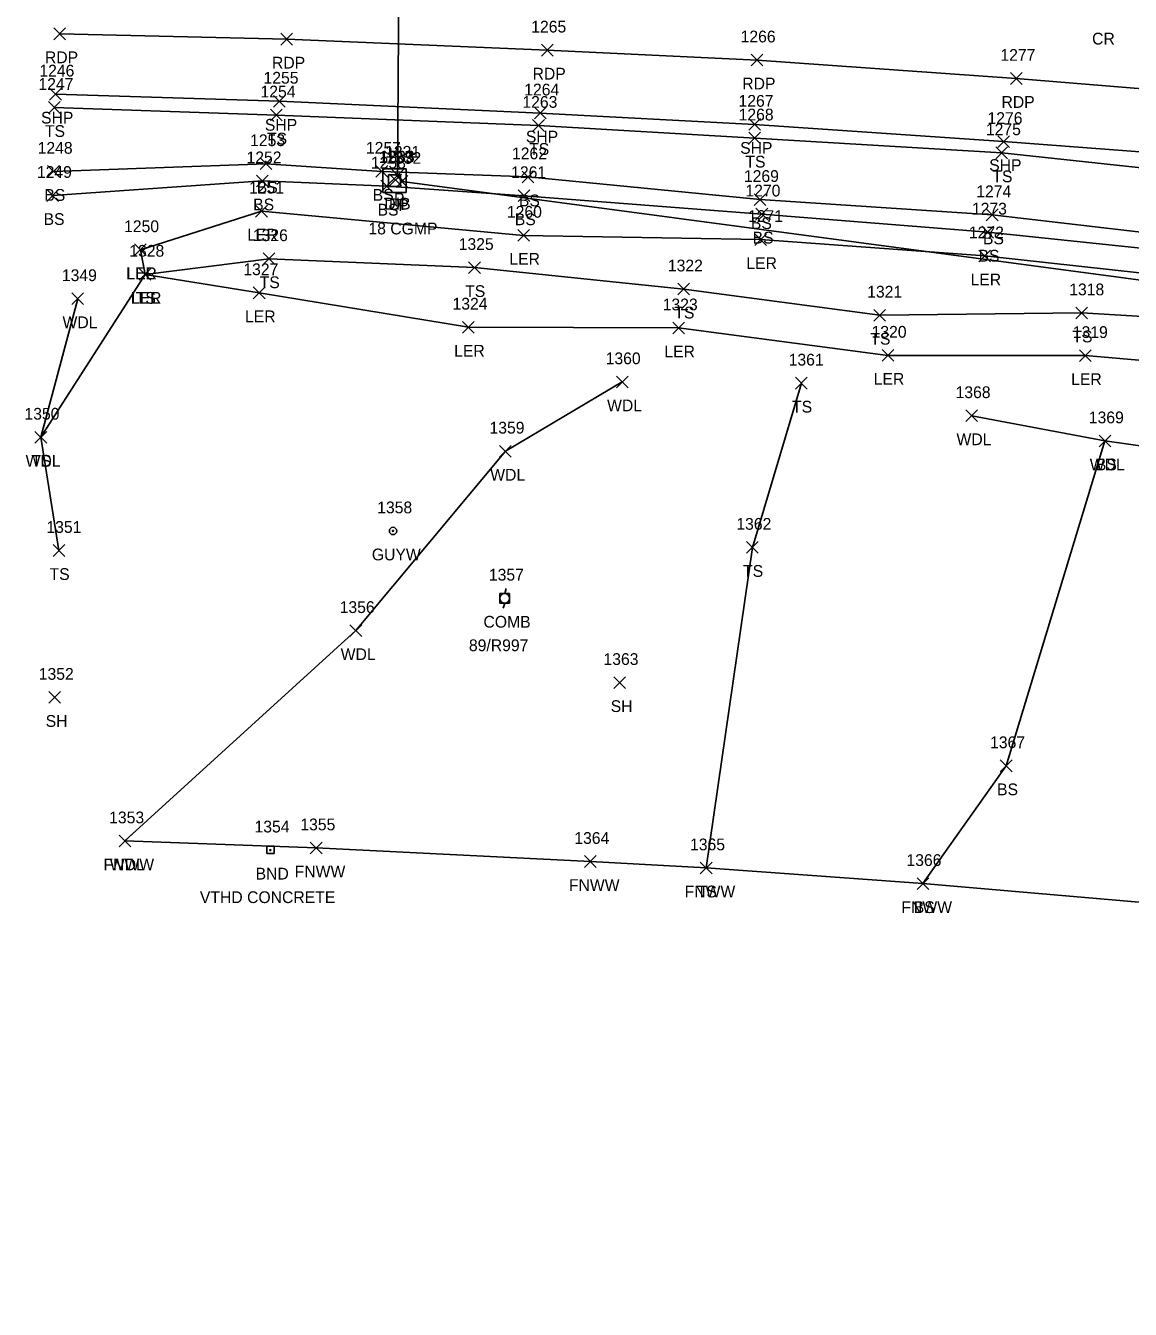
# Model space of a CAD drawing. Extents: x 1629176 to 1637209, y 606063 to 610167.
# Drawn here: x 1629176.2 to 1629364, y 606838.2 to 607056.5 of the extents above; entities that cross this region are included whole.
import ezdxf

# ---------------------------------------------------------------- set-up
doc = ezdxf.new("R2010")
doc.units = 0
for name, color, linetype in [('D_A', 7, 'Continuous'), ('D_C', 7, 'Continuous'), ('D_I', 7, 'Continuous'), ('D_TIC', 7, 'Continuous'), ('DCP', 7, 'Continuous'), ('DS', 7, 'Continuous'), ('L_A', 7, 'Continuous'), ('L_I', 7, 'Continuous'), ('L_TIC', 7, 'Continuous'), ('LARO', 7, 'Continuous'), ('LAWA', 7, 'Continuous'), ('LELB', 7, 'Continuous'), ('LFNC', 7, 'Continuous'), ('M_A', 7, 'Continuous'), ('M_C', 7, 'Continuous'), ('M_I', 7, 'Continuous'), ('MHBP', 7, 'Continuous'), ('P_A', 7, 'Continuous'), ('P_I', 7, 'Continuous'), ('P_TIC', 7, 'Continuous'), ('PET', 7, 'Continuous'), ('PSP', 7, 'Continuous'), ('U_A', 7, 'Continuous'), ('U_C', 7, 'Continuous'), ('U_I', 7, 'Continuous'), ('UP', 7, 'Continuous'), ('UPGW', 7, 'Continuous')]:
    doc.layers.add(name, color=color, linetype=linetype)

msp = doc.modelspace()

# ---------------------------------------------------------------- linework, layer by layer
at = {"layer": 'D_TIC'}
for points in [[(1629238.07, 607029.21), (1629240.07, 607031.21)], [(1629240.07, 607029.21), (1629238.07, 607031.21)], [(1629238.44, 607030.02), (1629240.44, 607032.02)], [(1629240.44, 607030.02), (1629238.44, 607032.02)], [(1629239.18, 607028.98), (1629241.18, 607030.98)], [(1629241.18, 607028.98), (1629239.18, 607030.98)]]:
    msp.add_lwpolyline(points, dxfattribs=at)
at = {"layer": 'DCP'}
for points in [[(1629239.94, 607104.56), (1629239.44, 607031.02)], [(1629240.18, 607029.98), (1629577.96, 606984.89)]]:
    msp.add_lwpolyline(points, dxfattribs=at)
at = {"layer": 'DS'}
for p, q in [((1629236.91, 607032.13), (1629240.91, 607032.13)), ((1629236.91, 607028.13), (1629236.91, 607032.13)), ((1629240.91, 607032.13), (1629240.91, 607028.13)), ((1629237.91, 607029.13), (1629237.91, 607031.13)), ((1629237.91, 607031.13), (1629239.91, 607031.13)), ((1629238.92, 607030.13), (1629238.92, 607030.13)), ((1629238.92, 607030.13), (1629238.92, 607030.13)), ((1629239.91, 607031.13), (1629239.91, 607029.13)), ((1629240.91, 607028.13), (1629236.91, 607028.13)), ((1629239.91, 607029.13), (1629237.91, 607029.13))]:
    msp.add_line(p, q, dxfattribs=at)
at = {"layer": 'L_TIC'}
for points in [[(1629180.05, 607041.55), (1629182.05, 607043.55)], [(1629182.05, 607041.55), (1629180.05, 607043.55)], [(1629217.81, 607040.26), (1629219.81, 607042.26)], [(1629219.81, 607040.26), (1629217.81, 607042.26)], [(1629262.39, 607038.5), (1629264.39, 607040.5)], [(1629264.39, 607038.5), (1629262.39, 607040.5)], [(1629299.16, 607036.35), (1629301.16, 607038.35)], [(1629301.16, 607036.35), (1629299.16, 607038.35)], [(1629341.16, 607033.85), (1629343.16, 607035.85)], [(1629343.16, 607033.85), (1629341.16, 607035.85)], [(1629179.91, 607030.69), (1629181.91, 607032.69)], [(1629181.91, 607030.69), (1629179.91, 607032.69)], [(1629216.04, 607031.99), (1629218.04, 607033.99)], [(1629218.04, 607031.99), (1629216.04, 607033.99)], [(1629235.75, 607030.7), (1629237.75, 607032.7)], [(1629237.75, 607030.7), (1629235.75, 607032.7)], [(1629215.43, 607029.07), (1629217.43, 607031.07)], [(1629217.43, 607029.07), (1629215.43, 607031.07)], [(1629236.58, 607028.18), (1629238.58, 607030.18)], [(1629238.58, 607028.18), (1629236.58, 607030.18)], [(1629260.62, 607029.75), (1629262.62, 607031.75)], [(1629262.62, 607029.75), (1629260.62, 607031.75)], [(1629179.79, 607026.59), (1629181.79, 607028.59)], [(1629181.79, 607026.59), (1629179.79, 607028.59)], [(1629259.92, 607026.55), (1629261.92, 607028.55)], [(1629261.92, 607026.55), (1629259.92, 607028.55)], [(1629300.07, 607025.9), (1629302.07, 607027.9)], [(1629302.07, 607025.9), (1629300.07, 607027.9)], [(1629215.28, 607023.93), (1629217.28, 607025.93)], [(1629217.28, 607023.93), (1629215.28, 607025.93)], [(1629300.36, 607023.43), (1629302.36, 607025.43)], [(1629302.36, 607023.43), (1629300.36, 607025.43)], [(1629339.53, 607023.3), (1629341.53, 607025.3)], [(1629341.53, 607023.3), (1629339.53, 607025.3)], [(1629259.85, 607019.82), (1629261.85, 607021.82)], [(1629261.85, 607019.82), (1629259.85, 607021.82)], [(1629338.78, 607020.36), (1629340.78, 607022.36)], [(1629340.78, 607020.36), (1629338.78, 607022.36)], [(1629194.7, 607017.37), (1629196.7, 607019.37)], [(1629196.7, 607017.37), (1629194.7, 607019.37)], [(1629194.7, 607017.37), (1629196.7, 607019.37)], [(1629196.7, 607017.37), (1629194.7, 607019.37)], [(1629300.15, 607019.1), (1629302.15, 607021.1)], [(1629302.15, 607019.1), (1629300.15, 607021.1)], [(1629216.57, 607015.84), (1629218.57, 607017.84)], [(1629218.57, 607015.84), (1629216.57, 607017.84)], [(1629338.28, 607016.31), (1629340.28, 607018.31)], [(1629340.28, 607016.31), (1629338.28, 607018.31)], [(1629195.49, 607013.19), (1629197.49, 607015.19)], [(1629197.49, 607013.19), (1629195.49, 607015.19)], [(1629195.49, 607013.19), (1629197.49, 607015.19)], [(1629197.49, 607013.19), (1629195.49, 607015.19)], [(1629195.49, 607013.19), (1629197.49, 607015.19)], [(1629197.49, 607013.19), (1629195.49, 607015.19)], [(1629251.51, 607014.34), (1629253.51, 607016.34)], [(1629253.51, 607014.34), (1629251.51, 607016.34)], [(1629287.08, 607010.69), (1629289.08, 607012.69)], [(1629289.08, 607010.69), (1629287.08, 607012.69)], [(1629184.04, 607009.04), (1629186.04, 607011.04)], [(1629186.04, 607009.04), (1629184.04, 607011.04)], [(1629214.89, 607010.05), (1629216.89, 607012.05)], [(1629216.89, 607010.05), (1629214.89, 607012.05)], [(1629320.41, 607006.24), (1629322.41, 607008.24)], [(1629322.41, 607006.24), (1629320.41, 607008.24)], [(1629354.77, 607006.63), (1629356.77, 607008.63)], [(1629356.77, 607006.63), (1629354.77, 607008.63)], [(1629250.47, 607004.2), (1629252.47, 607006.2)], [(1629252.47, 607004.2), (1629250.47, 607006.2)], [(1629286.21, 607004.07), (1629288.21, 607006.07)], [(1629288.21, 607004.07), (1629286.21, 607006.07)], [(1629321.81, 606999.42), (1629323.81, 607001.42)], [(1629323.81, 606999.42), (1629321.81, 607001.42)], [(1629355.39, 606999.37), (1629357.39, 607001.37)], [(1629357.39, 606999.37), (1629355.39, 607001.37)], [(1629276.64, 606994.91), (1629278.64, 606996.91)], [(1629278.64, 606994.91), (1629276.64, 606996.91)], [(1629307.1, 606994.69), (1629309.1, 606996.69)], [(1629309.1, 606994.69), (1629307.1, 606996.69)], [(1629336.05, 606989.15), (1629338.05, 606991.15)], [(1629338.05, 606989.15), (1629336.05, 606991.15)], [(1629177.76, 606985.49), (1629179.76, 606987.49)], [(1629179.76, 606985.49), (1629177.76, 606987.49)], [(1629177.76, 606985.49), (1629179.76, 606987.49)], [(1629179.76, 606985.49), (1629177.76, 606987.49)], [(1629358.72, 606984.87), (1629360.72, 606986.87)], [(1629360.72, 606984.87), (1629358.72, 606986.87)], [(1629358.72, 606984.87), (1629360.72, 606986.87)], [(1629360.72, 606984.87), (1629358.72, 606986.87)], [(1629256.76, 606983.12), (1629258.76, 606985.12)], [(1629258.76, 606983.12), (1629256.76, 606985.12)], [(1629180.84, 606966.24), (1629182.84, 606968.24)], [(1629182.84, 606966.24), (1629180.84, 606968.24)], [(1629298.77, 606966.77), (1629300.77, 606968.77)], [(1629300.77, 606966.77), (1629298.77, 606968.77)], [(1629231.33, 606952.62), (1629233.33, 606954.62)], [(1629233.33, 606952.62), (1629231.33, 606954.62)], [(1629276.18, 606943.79), (1629278.18, 606945.79)], [(1629278.18, 606943.79), (1629276.18, 606945.79)], [(1629180.1, 606941.27), (1629182.1, 606943.27)], [(1629182.1, 606941.27), (1629180.1, 606943.27)], [(1629341.92, 606929.64), (1629343.92, 606931.64)], [(1629343.92, 606929.64), (1629341.92, 606931.64)], [(1629192.07, 606916.87), (1629194.07, 606918.87)], [(1629194.07, 606916.87), (1629192.07, 606918.87)], [(1629192.07, 606916.87), (1629194.07, 606918.87)], [(1629194.07, 606916.87), (1629192.07, 606918.87)], [(1629224.59, 606915.68), (1629226.59, 606917.68)], [(1629226.59, 606915.68), (1629224.59, 606917.68)], [(1629271.22, 606913.37), (1629273.22, 606915.37)], [(1629273.22, 606913.37), (1629271.22, 606915.37)], [(1629290.9, 606912.28), (1629292.9, 606914.28)], [(1629292.9, 606912.28), (1629290.9, 606914.28)], [(1629290.9, 606912.28), (1629292.9, 606914.28)], [(1629292.9, 606912.28), (1629290.9, 606914.28)], [(1629327.76, 606909.62), (1629329.76, 606911.62)], [(1629329.76, 606909.62), (1629327.76, 606911.62)], [(1629327.76, 606909.62), (1629329.76, 606911.62)], [(1629329.76, 606909.62), (1629327.76, 606911.62)]]:
    msp.add_lwpolyline(points, dxfattribs=at)
at = {"layer": 'LARO'}
for points in [[(1629195.7, 607018.37), (1629216.28, 607024.93), (1629260.85, 607020.82), (1629301.15, 607020.1), (1629339.28, 607017.31), (1629382.1, 607012.64), (1629421.37, 607007.8), (1629464.6, 607001.62), (1629499.59, 606997.83), (1629501.87, 606992.79), (1629475.23, 606987.4), (1629447.18, 606989.2), (1629420.24, 606995.74), (1629384.31, 606997.97), (1629356.39, 607000.37), (1629322.81, 607000.42), (1629287.21, 607005.07), (1629251.47, 607005.2), (1629215.89, 607011.05), (1629196.49, 607014.19)], [(1629195.7, 607018.37), (1629196.49, 607014.19)]]:
    msp.add_lwpolyline(points, dxfattribs=at)
at = {"layer": 'LAWA'}
for points in [[(1629185.04, 607010.04), (1629178.76, 606986.49)], [(1629193.07, 606917.87), (1629232.33, 606953.62), (1629257.76, 606984.12), (1629277.64, 606995.91)], [(1629337.05, 606990.15), (1629359.72, 606985.87), (1629387.4, 606981.99), (1629441.76, 606976.24), (1629468.09, 606974.56), (1629493.34, 606966.73), (1629509.72, 606984.93)]]:
    msp.add_lwpolyline(points, dxfattribs=at)
at = {"layer": 'LELB'}
for points in [[(1629181.05, 607042.55), (1629218.81, 607041.26), (1629263.39, 607039.5), (1629300.16, 607037.35), (1629342.16, 607034.85), (1629381.18, 607030.68), (1629425.17, 607026.98), (1629465.04, 607022.58), (1629504.73, 607017.28), (1629537.12, 607012.67), (1629575, 607007.04)], [(1629180.91, 607031.69), (1629217.04, 607032.99), (1629236.75, 607031.7), (1629261.62, 607030.75), (1629301.07, 607026.9), (1629340.53, 607024.3), (1629381.42, 607019.52), (1629422.38, 607016.25), (1629464.23, 607011.91), (1629501.84, 607005.16), (1629533.54, 606997.75), (1629552.06, 606981.06), (1629551.51, 606957.3), (1629544.06, 606930), (1629529.36, 606888.4)], [(1629180.79, 607027.59), (1629216.43, 607030.07), (1629237.58, 607029.18), (1629260.92, 607027.55), (1629301.36, 607024.43), (1629339.78, 607021.36), (1629381.51, 607017.02), (1629421.62, 607012.3), (1629464.34, 607007.18), (1629501.12, 607001.75), (1629533.84, 606992.61), (1629552.06, 606981.06)], [(1629501.87, 606992.79), (1629480.98, 606995.23), (1629440.33, 607000.41), (1629421.47, 607000.71), (1629385.03, 607005.87), (1629355.77, 607007.63), (1629321.41, 607007.24), (1629288.08, 607011.69), (1629252.51, 607015.34), (1629217.57, 607016.84), (1629196.49, 607014.19), (1629178.76, 606986.49), (1629181.84, 606967.24)], [(1629308.1, 606995.69), (1629299.77, 606967.77), (1629291.9, 606913.28)], [(1629328.76, 606910.62), (1629342.92, 606930.64), (1629359.72, 606985.87)]]:
    msp.add_lwpolyline(points, dxfattribs=at)
at = {"layer": 'LFNC'}
msp.add_lwpolyline([(1629193.07, 606917.87), (1629225.59, 606916.68), (1629272.22, 606914.37), (1629291.9, 606913.28), (1629328.76, 606910.62), (1629372.75, 606906.84), (1629412.15, 606903.01), (1629459.35, 606897.68), (1629481.55, 606894.63), (1629529.36, 606888.4), (1629556.45, 606884.22), (1629596.1, 606877.05), (1629651.99, 606865.79), (1629687.21, 606857.94), (1629709.84, 606852.4), (1629726.11, 606849.55), (1629738.25, 606845.85), (1629771.23, 606838.25)], dxfattribs=at)
at = {"layer": 'MHBP'}
for p, q in [((1629218.44, 606916.97), (1629217.19, 606916.97)), ((1629217.19, 606916.97), (1629217.19, 606915.72)), ((1629218.44, 606916.97), (1629217.19, 606916.97)), ((1629217.19, 606916.97), (1629217.19, 606915.72)), ((1629218.44, 606915.72), (1629218.44, 606916.97)), ((1629218.44, 606915.72), (1629218.44, 606916.97)), ((1629217.19, 606915.72), (1629218.44, 606915.72)), ((1629217.19, 606915.72), (1629218.44, 606915.72))]:
    msp.add_line(p, q, dxfattribs=at)
msp.add_circle((1629217.79, 606916.31), 0.0833, dxfattribs=at)
at = {"layer": 'P_TIC'}
for points in [[(1629180.97, 607054.08), (1629182.97, 607056.08)], [(1629182.97, 607054.08), (1629180.97, 607056.08)], [(1629219.58, 607053.17), (1629221.58, 607055.17)], [(1629221.58, 607053.17), (1629219.58, 607055.17)], [(1629263.89, 607051.3), (1629265.89, 607053.3)], [(1629265.89, 607051.3), (1629263.89, 607053.3)], [(1629299.55, 607049.62), (1629301.55, 607051.62)], [(1629301.55, 607049.62), (1629299.55, 607051.62)], [(1629343.63, 607046.49), (1629345.63, 607048.49)], [(1629345.63, 607046.49), (1629343.63, 607048.49)], [(1629180.26, 607043.82), (1629182.26, 607045.82)], [(1629182.26, 607043.82), (1629180.26, 607045.82)], [(1629218.33, 607042.61), (1629220.33, 607044.61)], [(1629220.33, 607042.61), (1629218.33, 607044.61)], [(1629262.7, 607040.6), (1629264.7, 607042.6)], [(1629264.7, 607040.6), (1629262.7, 607042.6)], [(1629299.14, 607038.68), (1629301.14, 607040.68)], [(1629301.14, 607038.68), (1629299.14, 607040.68)], [(1629341.49, 607035.76), (1629343.49, 607037.76)], [(1629343.49, 607035.76), (1629341.49, 607037.76)]]:
    msp.add_lwpolyline(points, dxfattribs=at)
at = {"layer": 'PET'}
msp.add_lwpolyline([(1629181.97, 607055.08), (1629220.58, 607054.17), (1629264.89, 607052.3), (1629300.55, 607050.62), (1629344.63, 607047.49), (1629382.7, 607044.36), (1629427.5, 607039.91), (1629466.96, 607035.43), (1629507.21, 607030.19), (1629538.75, 607025.9), (1629578.99, 607019.69), (1629624.23, 607012.05), (1629673.21, 607003.11), (1629718.04, 606993.87), (1629764.48, 606983.46), (1629805.04, 606973.93), (1629842.82, 606964.4), (1629884.8, 606953.15), (1629930.25, 606940.34), (1629964.97, 606930.13), (1630005.89, 606916.45), (1630050.76, 606901.68), (1630096.23, 606885.67)], dxfattribs=at)
at = {"layer": 'PSP'}
msp.add_lwpolyline([(1629181.26, 607044.82), (1629219.33, 607043.61), (1629263.7, 607041.6), (1629300.14, 607039.68), (1629342.49, 607036.76), (1629381.41, 607033.8), (1629425.61, 607029.43), (1629465.11, 607025.03), (1629505.36, 607019.79), (1629537.56, 607015.39), (1629576.08, 607009.38), (1629623.28, 607001.72), (1629671.03, 606992.73), (1629715.19, 606983.38), (1629761.23, 606973.52), (1629802.25, 606963.72), (1629839.3, 606954.1), (1629871.33, 606945.94), (1629930.37, 606928.51), (1629965.2, 606918.43), (1630003.07, 606906.25), (1630045.28, 606892.75), (1630092.08, 606875.64)], dxfattribs=at)
at = {"layer": 'UP'}
for p, q in [((1629257.89, 606960.79), (1629257.64, 606959.96)), ((1629256.81, 606958.29), (1629256.81, 606959.96)), ((1629256.81, 606959.96), (1629258.47, 606959.96)), ((1629258.47, 606958.29), (1629256.81, 606958.29)), ((1629257.39, 606957.46), (1629257.64, 606958.29)), ((1629257.64, 606959.13), (1629257.64, 606959.13)), ((1629258.47, 606959.96), (1629258.47, 606958.29))]:
    msp.add_line(p, q, dxfattribs=at)
msp.add_circle((1629257.64, 606959.13), 0.833, dxfattribs=at)
at = {"layer": 'UPGW'}
for radius in [0.625, 0.0833]:
    msp.add_circle((1629238.65, 606970.57), radius, dxfattribs=at)

# ---------------------------------------------------------------- texts
at = {"layer": 'D_A'}
for s, p in [('P', (1629238.82, 607026.02)), ('DIB', (1629237.18, 607025.21)), ('DI', (1629237.97, 607025.13)), ('P', (1629239.56, 607024.98))]:
    msp.add_text(s, height=2, dxfattribs=at).set_placement(p)
at = {"layer": 'D_C'}
msp.add_text('18 CGMP', height=2, dxfattribs=at).set_placement((1629234.47, 607020.98))
at = {"layer": 'D_I'}
for s, p in [('1259', (1629236.22, 607033.13)), ('1333', (1629236.38, 607033.21)), ('1331', (1629237.31, 607034.02)), ('1332', (1629237.49, 607032.98))]:
    msp.add_text(s, height=2, dxfattribs=at).set_placement(p)
at = {"layer": 'L_A'}
for s, p in [('TS', (1629179.46, 607037.55)), ('TS', (1629217.22, 607036.26)), ('TS', (1629261.8, 607034.5)), ('TS', (1629298.57, 607032.35)), ('BS', (1629215.48, 607027.99)), ('TS', (1629340.57, 607029.85)), ('BS', (1629179.35, 607026.69)), ('BS', (1629235.19, 607026.7)), ('BS', (1629260.06, 607025.75)), ('BS', (1629214.87, 607025.07)), ('BS', (1629236.02, 607024.18)), ('BS', (1629179.23, 607022.59)), ('BS', (1629259.36, 607022.55)), ('BS', (1629299.51, 607021.9)), ('LER', (1629213.87, 607019.93)), ('BS', (1629299.8, 607019.43)), ('BS', (1629338.97, 607019.3)), ('LER', (1629258.43, 607015.82)), ('LER', (1629298.73, 607015.1)), ('BS', (1629338.22, 607016.36)), ('LER', (1629193.28, 607013.37)), ('LEL', (1629193.34, 607013.37)), ('TS', (1629215.98, 607011.84)), ('LER', (1629336.86, 607012.31)), ('LER', (1629194.07, 607009.19)), ('LEL', (1629194.13, 607009.19)), ('TS', (1629194.9, 607009.19)), ('TS', (1629250.92, 607010.34)), ('TS', (1629286.49, 607006.69)), ('WDL', (1629182.45, 607005.04)), ('LER', (1629213.48, 607006.05)), ('TS', (1629319.82, 607002.24)), ('TS', (1629354.18, 607002.63)), ('LER', (1629249.05, 607000.2)), ('LER', (1629284.79, 607000.07)), ('LER', (1629320.39, 606995.42)), ('LER', (1629353.97, 606995.37)), ('WDL', (1629275.05, 606990.91)), ('TS', (1629306.51, 606990.69)), ('WDL', (1629334.47, 606985.15)), ('WDL', (1629176.18, 606981.49)), ('TS', (1629177.17, 606981.49)), ('WDL', (1629357.13, 606980.87)), ('BS', (1629358.16, 606980.87)), ('WDL', (1629255.18, 606979.12)), ('TS', (1629298.18, 606962.77)), ('TS', (1629180.25, 606962.24)), ('WDL', (1629229.75, 606948.62)), ('SH', (1629275.67, 606939.79)), ('SH', (1629179.59, 606937.27)), ('BS', (1629341.37, 606925.64)), ('FNWW', (1629189.41, 606912.87)), ('WDL', (1629190.49, 606912.87)), ('FNWW', (1629221.93, 606911.68)), ('FNWW', (1629268.56, 606909.37)), ('FNWW', (1629288.24, 606908.28)), ('TS', (1629290.31, 606908.28)), ('FNWW', (1629325.1, 606905.62)), ('BS', (1629327.2, 606905.62))]:
    msp.add_text(s, height=2, dxfattribs=at).set_placement(p)
at = {"layer": 'L_I'}
for s, p in [('1247', (1629178.35, 607045.55)), ('1254', (1629216.12, 607044.26)), ('1263', (1629260.65, 607042.5)), ('1268', (1629297.42, 607040.35)), ('1275', (1629339.47, 607037.85)), ('1248', (1629178.22, 607034.69)), ('1253', (1629214.35, 607035.99)), ('1257', (1629234.05, 607034.7)), ('1252', (1629213.74, 607033.07)), ('1262', (1629258.88, 607033.75)), ('1249', (1629178.09, 607030.59)), ('1258', (1629234.89, 607032.18)), ('1261', (1629258.74, 607030.55)), ('1251', (1629214.16, 607027.93)), ('1269', (1629298.32, 607029.9)), ('1270', (1629298.58, 607027.43)), ('1274', (1629337.83, 607027.3)), ('1260', (1629258.02, 607023.82)), ('1273', (1629337.09, 607024.36)), ('1250', (1629192.92, 607021.37)), ('1250', (1629192.92, 607021.37)), ('1271', (1629299.02, 607023.1)), ('1326', (1629214.82, 607019.84)), ('1272', (1629336.58, 607020.31)), ('1328', (1629193.8, 607017.19)), ('1328', (1629193.8, 607017.19)), ('1328', (1629193.8, 607017.19)), ('1325', (1629249.82, 607018.34)), ('1349', (1629182.34, 607013.04)), ('1327', (1629213.2, 607014.05)), ('1322', (1629285.39, 607014.69)), ('1318', (1629353.64, 607010.63)), ('1321', (1629319.28, 607010.24)), ('1324', (1629248.77, 607008.2)), ('1323', (1629284.51, 607008.07)), ('1320', (1629320.03, 607003.42)), ('1319', (1629354.25, 607003.37)), ('1360', (1629274.81, 606998.91)), ('1361', (1629305.93, 606998.69)), ('1368', (1629334.31, 606993.15)), ('1350', (1629175.98, 606989.49)), ('1350', (1629175.98, 606989.49)), ('1369', (1629356.97, 606988.87)), ('1369', (1629356.97, 606988.87)), ('1359', (1629255.06, 606987.12)), ('1351', (1629179.71, 606970.24)), ('1362', (1629297.03, 606970.77)), ('1356', (1629229.58, 606956.62)), ('1363', (1629274.44, 606947.79)), ('1352', (1629178.41, 606945.27)), ('1367', (1629340.18, 606933.64)), ('1353', (1629190.38, 606920.87)), ('1353', (1629190.38, 606920.87)), ('1355', (1629222.89, 606919.68)), ('1364', (1629269.48, 606917.37)), ('1365', (1629289.16, 606916.28)), ('1365', (1629289.16, 606916.28)), ('1366', (1629325.96, 606913.62)), ('1366', (1629325.96, 606913.62))]:
    msp.add_text(s, height=2, dxfattribs=at).set_placement(p)
at = {"layer": 'M_A'}
msp.add_text('BND', height=2, dxfattribs=at).set_placement((1629215.28, 606911.31))
at = {"layer": 'M_C'}
msp.add_text('VTHD CONCRETE', height=2, dxfattribs=at).set_placement((1629205.81, 606907.31))
at = {"layer": 'M_I'}
msp.add_text('1354', height=2, dxfattribs=at).set_placement((1629215.1, 606919.31))
at = {"layer": 'P_A'}
for s, p in [('CR', (1629357.53, 607053.26)), ('RDP', (1629179.46, 607050.08)), ('RDP', (1629218.07, 607049.17)), ('RDP', (1629262.38, 607047.3)), ('RDP', (1629298.04, 607045.62)), ('RDP', (1629342.12, 607042.49)), ('SHP', (1629178.8, 607039.82)), ('SHP', (1629216.86, 607038.61)), ('SHP', (1629261.24, 607036.6)), ('SHP', (1629297.68, 607034.68)), ('SHP', (1629340.03, 607031.76))]:
    msp.add_text(s, height=2, dxfattribs=at).set_placement(p)
at = {"layer": 'P_I'}
for s, p in [('1265', (1629262.15, 607055.3)), ('1266', (1629297.76, 607053.62)), ('1277', (1629341.94, 607050.49)), ('1246', (1629178.51, 607047.82)), ('1255', (1629216.63, 607046.61)), ('1264', (1629260.96, 607044.6)), ('1267', (1629297.4, 607042.68)), ('1276', (1629339.74, 607039.76))]:
    msp.add_text(s, height=2, dxfattribs=at).set_placement(p)
at = {"layer": 'U_A'}
for s, p in [('GUYW', (1629235.05, 606965.57)), ('COMB', (1629254.03, 606954.13))]:
    msp.add_text(s, height=2, dxfattribs=at).set_placement(p)
at = {"layer": 'U_C'}
msp.add_text('89/R997', height=2, dxfattribs=at).set_placement((1629251.56, 606950.13))
at = {"layer": 'U_I'}
for s, p in [('1358', (1629235.96, 606973.57)), ('1357', (1629254.95, 606962.13))]:
    msp.add_text(s, height=2, dxfattribs=at).set_placement(p)

doc.saveas('drawing.dxf')
